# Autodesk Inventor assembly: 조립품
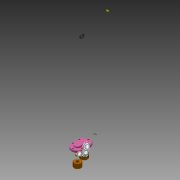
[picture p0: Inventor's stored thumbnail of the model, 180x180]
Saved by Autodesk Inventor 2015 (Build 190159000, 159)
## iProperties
Created: 2020-09
Part Number: 조립품
Document SubType Name: Assembly
Designer: Line503_02
Author: Line503_02
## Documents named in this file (11)
- C:\Users\Line503_02\Desktop\700906V1020\조립품.iam
- C:\Users\Line503_02\Desktop\700906V1020\본체.ipt
- C:\Users\Line503_02\Desktop\700906V1020\개스킷.ipt
- C:\Users\Line503_02\Desktop\700906V1020\메인축.ipt
- C:\Users\Line503_02\Desktop\700906V1020\베어링부시.ipt
- C:\Users\Line503_02\Desktop\700906V1020\볼트 M5.ipt
- C:\Users\Line503_02\Desktop\700906V1020\서브축.ipt
- C:\Users\Line503_02\Desktop\700906V1020\스퍼기어.ipt
- C:\Users\Line503_02\Desktop\700906V1020\오일 실 16 28 7.ipt
- C:\Users\Line503_02\Desktop\700906V1020\커버.ipt
- C:\Users\Line503_02\Desktop\700906V1020\키 6 x 6 x 18.ipt
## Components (1 placed, 1 different names)
1. 개스킷:1
